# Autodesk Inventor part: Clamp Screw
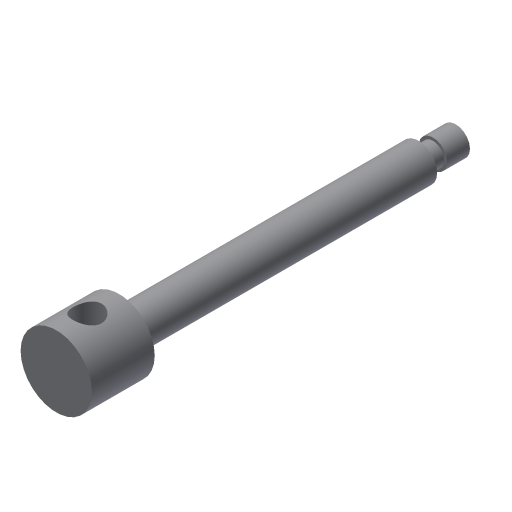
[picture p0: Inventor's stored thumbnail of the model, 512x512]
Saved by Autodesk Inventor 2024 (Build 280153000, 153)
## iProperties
Shininess: 77.0
Length Units: 11269
Angle Units: 11279
Time Units: 11290
Mass Units: 11283
Length Display Precision: 3
Angle Display Precision: 2
Created: 2002-02
Part Number: Clamp Screw
Document SubType Name: Modeling
Designer: ***
Density: 1 g/cm^3
Material: Generic
Appearance: Default
Density: 0.0
Volumn: 0.0
Area: 0.0
PropertySet Name: Model Information
Control State: 0
Master: False
Checked Out: False
Author: ***
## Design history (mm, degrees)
sketch "Sketch1"
  geometry: L1 (0, 140)-(5, 140); L2 (5, 140)-(5, 132); L3 (5, 132)-(4, 132); L4 (4, 132)-(4, 127); L5 (4, 127)-(6.5, 127); L6 (6.5, 127)-(6.5, 25); L7 (6.5, 25)-(4, 25); L8 (4, 25)-(4, 22); L9 (4, 22)-(12.5, 22); L10 (12.5, 22)-(12.5, 0); L11 (12.5, 0)-(0, 0); L12 (0, 0)-(0, 140)
  constraints: 24 end point, 10 parallel, 1 horizontal, 1 perpendicular
  dimensions: "d0" = 10 diameter of L2 L12; "d1" = 8 diameter of L4 L12; "d2" = 13 diameter of L6 L12; "d3" = 8 diameter of L7.end L12; "d4" = 25 diameter of L10 L12; "d5" = 3 distance from line of L7.end L9; "d6" = 8 distance of L1.end L2.end; "d7" = 13 vertical distance of L1.end L5.end; "d8" = 22 distance of L9.end L10.end; "d10" = 102 distance of L5.end L6.end
revolve "Revolution1" sketch "Sketch1" stored, may be unused: angle "d11" = 90 deg
sketch "Sketch3"
  geometry: L1 (-12.5, 0)-(12.5, 0) reference; C1 r 5 at (-0.113, 11)
  constraints: 1 centre point
  dimensions: "d13" = 10 diameter of C1; "d14" = 11 distance from line of L1 C1.centre
extrude "Extrusion1" cut sketch "Sketch3" extent not by distance; stored distance "d15" = 10; taper "d16" = 0 deg
body "Solid1"
